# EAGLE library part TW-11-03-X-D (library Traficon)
SAMTEC TW-10-03-X-D
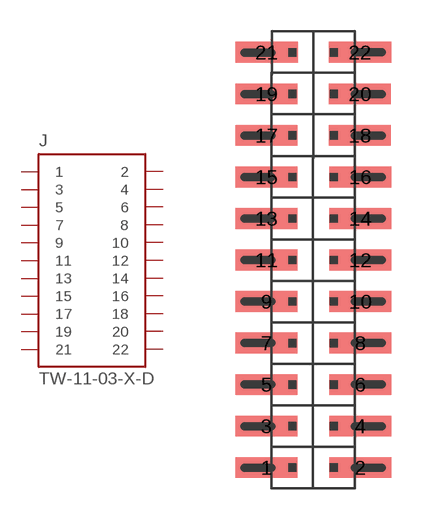
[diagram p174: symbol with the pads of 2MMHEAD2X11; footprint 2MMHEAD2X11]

Designator prefix J

## TW-11-03-X-D  [2MMHEAD2X11]
1  1  pas
2  2  pas
3  3  pas
4  4  pas
5  5  pas
6  6  pas
7  7  pas
8  8  pas
9  9  pas
10  10  pas
11  11  pas
12  12  pas
13  13  pas
14  14  pas
15  15  pas
16  16  pas
17  17
18  18
19  19
20  20
21  21
22  22

## Footprint 2MMHEAD2X11 (pad centres in mm)
smd 3 x 1: 1 -2.255,-10.002; 2 2.265,-10.002; 3 -2.255,-8.002; 4 2.265,-8.002; 5 -2.255,-6.002; 6 2.265,-6.002; 7 -2.255,-4.002; 8 2.265,-4.002; 9 -2.255,-2.002; 10 2.265,-2.002; 11 -2.255,-0.002; 12 2.265,-0.002; 13 -2.255,1.998; 14 2.265,1.998; 15 -2.255,3.998; 16 2.265,3.998; 17 -2.255,5.998; 18 2.245,5.998; 19 -2.255,7.998; 20 2.245,7.998; 21 -2.253,10.004; 22 2.247,10.004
